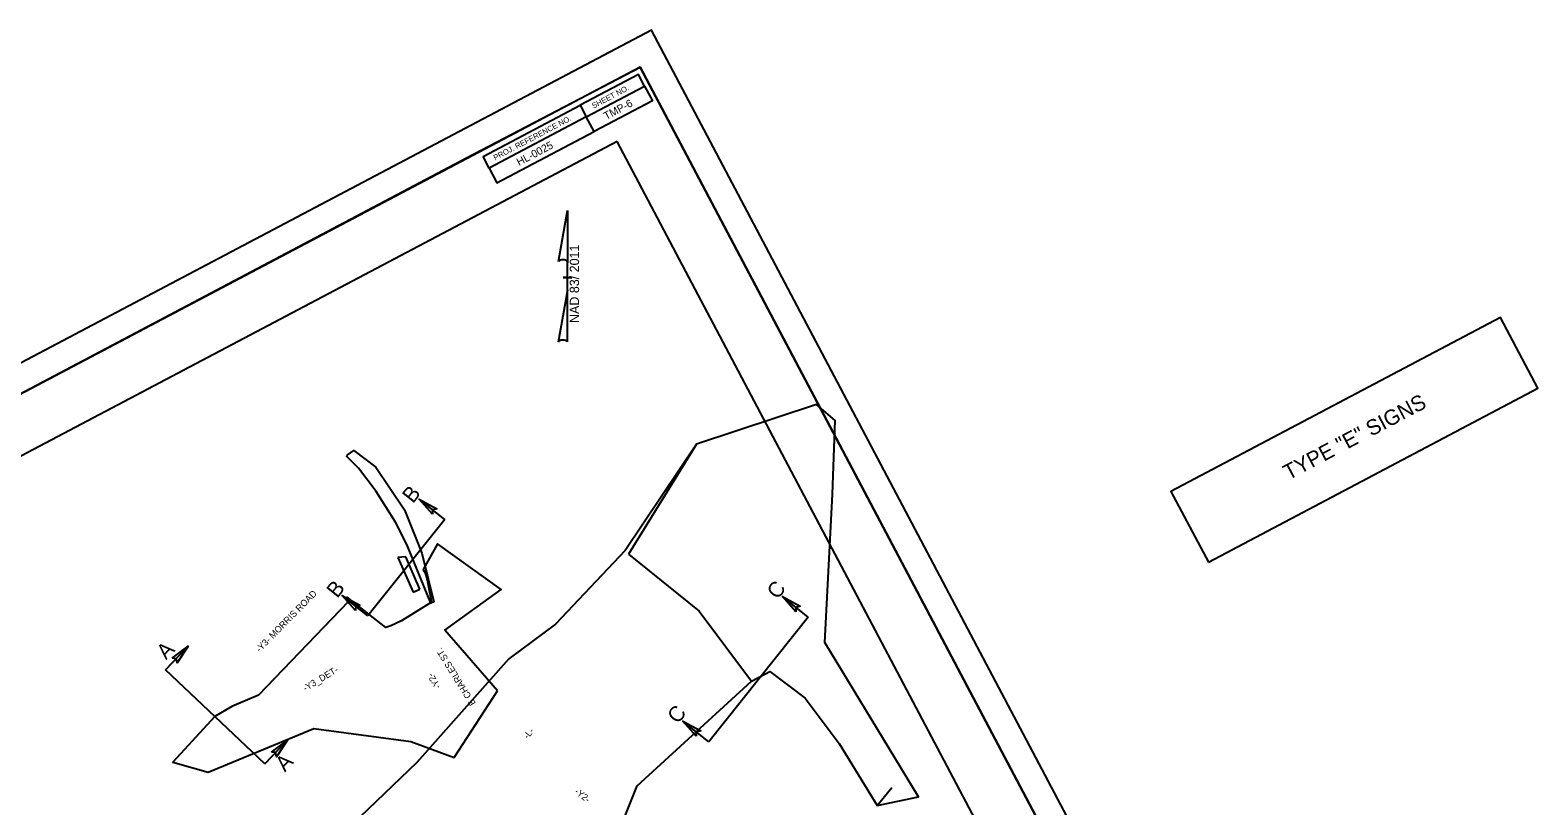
# Model space of a CAD drawing. Extents: x 1487052 to 1489663, y 496209 to 500965.
# Drawn here: x 1488265 to 1489637, y 499036 to 499742 of the extents above; entities that cross this region are included whole.
import ezdxf

# ---------------------------------------------------------------- set-up
doc = ezdxf.new("R2010")
doc.units = 0
for name, color, linetype in [('Default', 7, 'Continuous'), ('DEV TYPE 3 BARRICADE SECTION CELL', 7, 'Continuous'), ('DEV TYPE 3 BARRICADE SINGLE WITH R11-2 CELL', 7, 'Continuous'), ('Matchline', 7, 'Continuous'), ('Prop North Arrow NAD83 for Plan Sheets CELL', 7, 'Continuous'), ('Prop Terminator CELL', 7, 'Continuous'), ('Scratch_Level_0', 7, 'Continuous'), ('Scratch_Level_3', 7, 'Continuous'), ('Sheet Block Title CELL', 7, 'Continuous'), ('Sheet Plot Border Outside CELL', 7, 'Continuous'), ('Sheet Title CELL', 7, 'Continuous'), ('Text', 7, 'Continuous')]:
    doc.layers.add(name, color=color, linetype=linetype)

msp = doc.modelspace()

# ---------------------------------------------------------------- linework, layer by layer
at = {"layer": 'Default'}
msp.add_line((1489035.9, 499035.8), (1489049.3, 499052.3), dxfattribs=at)
at = {"layer": 'DEV TYPE 3 BARRICADE SINGLE WITH R11-2 CELL'}
msp.add_lwpolyline([(1488799.3, 499640.6), (1487561.2, 498986.9), (1488004.8, 498146.9), (1488782, 498557.2), (1488726.8, 498661.8), (1489187.6, 498905.1)], close=True, dxfattribs=at)
at = {"layer": 'Matchline'}
for p, q in [((1488642.4, 499296.2), (1488619, 499314.9)), ((1488642.4, 499296.2), (1488572.4, 499208.5)), ((1488572.4, 499208.5), (1488549, 499227.2)), ((1488973.1, 499207.4), (1488949.6, 499226.1)), ((1488973.1, 499207.4), (1488882.6, 499094)), ((1488388.3, 499159.3), (1488408.9, 499181.1)), ((1488478.6, 499073.8), (1488388.3, 499159.3)), ((1488882.6, 499094), (1488859.1, 499112.8)), ((1488478.6, 499073.8), (1488499.2, 499095.5))]:
    msp.add_line(p, q, dxfattribs=at)
at = {"layer": 'Prop North Arrow NAD83 for Plan Sheets CELL'}
for p, q in [((1488745.8, 499531.4), (1488754, 499577.8)), ((1488754, 499577.8), (1488754, 499577.8)), ((1488754, 499577.8), (1488754, 499577.8)), ((1488754, 499577.8), (1488754, 499530)), ((1488754, 499505.2), (1488754, 499531.4)), ((1488754, 499530), (1488754, 499531.3)), ((1488753.6, 499516.8), (1488750, 499516.8)), ((1488750, 499516.8), (1488750, 499516.8)), ((1488750.1, 499516.8), (1488758.1, 499516.8)), ((1488754, 499505.2), (1488745.7, 499457.9)), ((1488754.1, 499458.1), (1488754, 499505.2))]:
    msp.add_line(p, q, dxfattribs=at)
for centre, start_param, end_param in [((1488749.9, 499530.9), 0.216388, 2.908219), ((1488749.9, 499457.8), 0.201328, 3.141593)]:
    msp.add_ellipse(centre, major_axis=(4.23, -0.03), ratio=0.461098, start_param=start_param, end_param=end_param, dxfattribs=at)
at = {"layer": 'Prop Terminator CELL'}
for points in [[(1488631.1, 499301.2), (1488619, 499314.9), (1488635.1, 499306.1), (1488631.3, 499305)], [(1488561.1, 499213.6), (1488549, 499227.2), (1488565.1, 499218.4), (1488561.3, 499217.4)], [(1488961.8, 499212.4), (1488949.6, 499226.1), (1488965.8, 499217.3), (1488962, 499216.2)], [(1488394.3, 499170.1), (1488408.9, 499181.1), (1488398.8, 499165.7), (1488398.1, 499169.6)], [(1488871.3, 499099.1), (1488859.1, 499112.8), (1488875.3, 499104), (1488871.5, 499102.9)], [(1488484.6, 499084.6), (1488499.2, 499095.5), (1488489.1, 499080.2), (1488488.4, 499084.1)]]:
    msp.add_lwpolyline(points, close=True, dxfattribs=at)
at = {"layer": 'Scratch_Level_0'}
msp.add_line((1488771.2, 499663), (1488824.3, 499691), dxfattribs=at)
for points in [[(1488820.1, 499708.2), (1487493.7, 499007.8), (1487984, 498079.3), (1489310.4, 498779.7)], [(1488771.2, 499663), (1488824.3, 499691), (1488818.7, 499701.6), (1488765.6, 499673.6)], [(1488771.2, 499663), (1488824.3, 499691), (1488831.3, 499677.7), (1488778.2, 499649.7)], [(1488677.2, 499626.9), (1488765.6, 499673.6), (1488771.2, 499663), (1488682.8, 499616.3)], [(1488771.2, 499663), (1488682.8, 499616.3), (1488689.8, 499603), (1488778.2, 499649.7)]]:
    msp.add_lwpolyline(points, close=True, dxfattribs=at)
at = {"layer": 'Scratch_Level_3'}
for points in [[(1487493.7, 499007.8), (1488662.1, 499625.8), (1488820.1, 499708.2), (1489310.4, 498779.7), (1487984, 498079.3)], [(1487493.7, 499007.8), (1488662.1, 499625.8), (1488820.1, 499708.2), (1489310.4, 498779.7), (1487984, 498079.3)], [(1488809.7, 499264.8), (1488874, 499212.9), (1488921.5, 499149.2), (1488938.1, 499157.8), (1488970.3, 499133.5), (1489001.4, 499092.4), (1489035.9, 499035.8), (1489073.6, 499043.8), (1488988.2, 499184.2), (1488995.1, 499319.4), (1488997.6, 499386.6), (1488980.8, 499401.1), (1488871.5, 499364.9)], [(1488553.7, 499354.8), (1488559.5, 499359.1), (1488579.5, 499343.9), (1488605.6, 499305.1), (1488621.6, 499265.6), (1488632.5, 499221.5), (1488629.6, 499220.1), (1488608.3, 499273.1), (1488597.5, 499294), (1488579.9, 499321.9), (1488563.8, 499343.1), (1488553.2, 499353.8)], [(1488690.4, 499140.2), (1488642.4, 499195.5), (1488693.7, 499232.6), (1488635.8, 499274.1), (1488622.6, 499250.9), (1488624.6, 499247.7), (1488626.5, 499241.3), (1488630.2, 499221), (1488603, 499204.1), (1488593.4, 499199.5), (1488588.6, 499198.1), (1488553.5, 499225.7), (1488554.6, 499221.4), (1488472.9, 499136.4), (1488448.5, 499126), (1488433, 499117), (1488395, 499075.3), (1488427.2, 499066.3), (1488523.2, 499106.1), (1488611.5, 499094.2), (1488650.9, 499079.6)]]:
    msp.add_lwpolyline(points, close=True, dxfattribs=at)
for points in [[(1487860.6, 498348.6), (1487873.5, 498334.9), (1488052.4, 498393.7), (1488380.4, 498605.8), (1488680.8, 498962.7), (1488788.1, 498980.4), (1488817.5, 499053.9), (1488921.5, 499149.2), (1488934.2, 499155.9), (1488938.1, 499157.8), (1488970.3, 499133.5), (1489001.4, 499092.4), (1489035.9, 499035.8), (1489073.6, 499043.8), (1488988.2, 499184.2), (1488995.1, 499319.4), (1488997.6, 499386.6), (1488980.8, 499401.1), (1488871.5, 499364.9), (1488806.5, 499268.1), (1488743.2, 499201.1), (1488700.8, 499169.5), (1488617.1, 499075)], [(1488617.1, 499075), (1488135, 498612.7), (1488123.4, 498651), (1488013.4, 498588.9), (1488016.8, 498549), (1487814.9, 498435.1), (1487860.6, 498348.6)]]:
    msp.add_lwpolyline(points, dxfattribs=at)
at = {"layer": 'Sheet Block Title CELL'}
msp.add_lwpolyline([(1489337.3, 499257.5), (1489637.2, 499415.8), (1489603.2, 499480.2), (1489303.3, 499321.9)], close=True, dxfattribs=at)
at = {"layer": 'Sheet Plot Border Outside CELL'}
msp.add_lwpolyline([(1487851.5, 497981.1), (1489344.2, 498769.3), (1488830.6, 499742), (1487337.9, 498953.8)], close=True, dxfattribs=at)
at = {"layer": 'Text'}
for p, q in [((1488606.8, 499262.4), (1488599.7, 499261.6)), ((1488619.7, 499233), (1488606.8, 499262.4)), ((1488599.7, 499261.6), (1488613.6, 499230.3)), ((1488613.6, 499230.3), (1488619.7, 499233))]:
    msp.add_line(p, q, dxfattribs=at)

# ---------------------------------------------------------------- texts
at = {"layer": 'Default'}
for s, rotation, p in [('B', 51.3844, (1488613.4, 499310.3)), ('B', 51.3844, (1488544.5, 499224)), ('C', 51.3844, (1488945.2, 499222.8)), ('A', 46.5652, (1488388.8, 499168)), ('C', 51.3844, (1488854.6, 499109.5)), ('A', 46.5652, (1488496.9, 499065.9))]:
    msp.add_text(s, height=14, rotation=rotation, dxfattribs=at).set_placement(p)
at = {"layer": 'DEV TYPE 3 BARRICADE SECTION CELL'}
for s, rotation, p in [('-Y3- MORRIS ROAD', 45.4445, (1488473.9, 499175)), ('E CHARLES ST.', 121.7363, (1488670.8, 499129.1)), ('-Y3_DET-', 30.8418, (1488515.5, 499139.6)), ('-Y2-', 121.7363, (1488639.1, 499144.3)), ('-L-', 51.1156, (1488717.9, 499096)), ('-Y2-', 321.1156, (1488760, 499047.6))]:
    msp.add_text(s, height=6, rotation=rotation, dxfattribs=at).set_placement(p)
at = {"layer": 'Prop North Arrow NAD83 for Plan Sheets CELL'}
msp.add_text('NAD 83/ 2011', height=8.5, rotation=90, dxfattribs=at).set_placement((1488764.6, 499475.3))
at = {"layer": 'Scratch_Level_0'}
for s, height, rotation, p in [('SHEET NO.', 5, 27.8356, (1488777.8, 499670.4)), ('TMP-6', 7, 27.8351, (1488789.3, 499660.1)), ('PROJ. REFERENCE NO.', 4.999, 27.8356, (1488688.3, 499623.2)), ('HL-0025', 7, 27.8351, (1488710, 499618.2))]:
    msp.add_text(s, height=height, rotation=rotation, dxfattribs=at).set_placement(p)
at = {"layer": 'Sheet Title CELL'}
msp.add_text('TYPE "E" SIGNS', height=14, rotation=27.8343, dxfattribs=at).set_placement((1489410.2, 499331.9))

doc.saveas('drawing.dxf')
